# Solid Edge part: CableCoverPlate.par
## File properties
Author: morva
Template: iso metric part.par
Last saved by: morva
Revision: 15
Application: Solid Edge
Density: 1385.000 kg/m^3
Accuracy: 0.990
Username: morva
Material: PVC
Face Style: Tan
Fill Style: ANSI34(Plastic)
Virtual Style: Tan (Shiny)
Grouping: Non-metals\Plastics
LibraryName: Materials
Coef. of Thermal Exp: 9e-05
Thermal Conductivity: 1.5
Specific Heat: 0.0
Modulus of Elasticity: 2757903000.0
Poisson's Ratio: 0.4
Yield Stress: 6894757.0
Ultimate Stress: 0.0
Elongation: 0.0
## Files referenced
..\..\DeckAssemlby.asm
C:\Users\morva\OneDrive\Dokumentumok\egyetem\VII. félév\Szakdolgozat\3D modellek\DeckAssemlby.asm
v\Szakdolgozat\3D modellek\DeckAssemlby.asm
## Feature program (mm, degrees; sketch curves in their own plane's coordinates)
sketch for "unnamed Protrusion 1" plane through (0, 0, 0) normal (0, 0, 1) x-axis (1, 0, 0)
  line (-178, 25) -> (-178, -25)
  line (-178, -25) -> (178, -25)
  line (178, -25) -> (178, 25)
  line (178, 25) -> (-178, 25)
  dimension (linear) = 178
  dimension (linear) = 178
extrude "unnamed Protrusion 1" add finite 2 along -normal
extrude "ExtrudedCutout_1" cut finite 5.0762
sketch for "unnamed Cutout 1" plane through (0, 0, 0) normal (0, 0, 1) x-axis (1, 0, 0)
extrude "unnamed Cutout 1" cut through along -normal
chamfer "Chamfer_1" setback 2
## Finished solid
Body 1: solid body, 7 faces, 14 edges, 8 vertices.
  Faces by surface: plane 6, cylinder 1
  Edges by curve: line 12, circle 2
Bounding box of the edges (mm): 335.280 x 50.000 x 2.000, from (-178, -25, -2) to (157.28, 25, 0).
Cylindrical faces by radius (mm): R10 x1
Planar faces by outward normal: +y 1, +z 1, -x 1, -y 1, -z 1, oblique 1
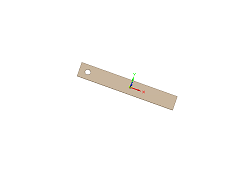
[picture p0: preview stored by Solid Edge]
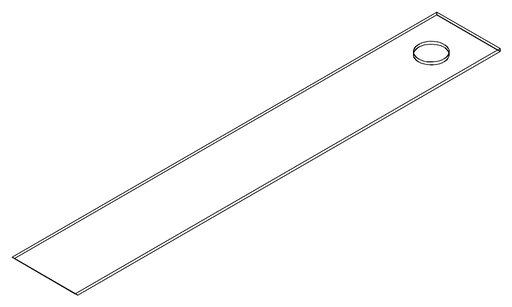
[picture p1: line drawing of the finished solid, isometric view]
